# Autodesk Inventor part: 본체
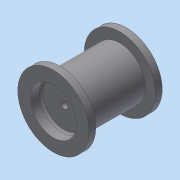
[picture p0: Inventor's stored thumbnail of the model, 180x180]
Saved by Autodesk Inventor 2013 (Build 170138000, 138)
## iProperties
Created: 2018-02
Part Number: 본체
Material: 일반
Document SubType Name: Modeling
Designer: Administrator
Density: 1 g/cm^3
Author: Administrator
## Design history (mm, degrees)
sketch "스케치3"
  geometry: L1 (0, 54)-(0, -54); L2 (0, 54)-(52.5, 54); L3 (52.5, 54)-(52.5, 44); L4 (52.5, 44)-(38, 44); L5 (38, 44)-(38, -44); L6 (38, -44)-(52.5, -44); L7 (52.5, -44)-(52.5, -54); L8 (52.5, -54)-(0, -54); L9 (37, 54)-(37, 47); L10 (37, 47)-(33, 47); L11 (33, 47)-(33, -32); L12 (33, -32)-(5, -32); L13 (5, -32)-(5, -38); L14 (5, -38)-(34, -38); L15 (34, -38)-(34, -54); 2 further points
  constraints: 30 end point, 7 perpendicular, 5 parallel, 2 equal length, 2 point on line, 1 coincident, 1 collinear, 1 horizontal, 1 midpoint, 1 vertical
  dimensions: "d0" = 108 distance of L1.start L1.end; "d2" = 10 distance of L2.end L3.end; "d3" = 76 diameter of L5 L1; "d4" = 105 diameter of L7 L1; "d5" = 68 diameter of L15 L1; "d6" = 10 diameter of L13 L1; "d7" = 16 distance between parallel lines of L8 L14; "d8" = 79 distance between parallel lines of L10 L12; "d9" = 7 distance between parallel lines of L2 L10; "d10" = 74 diameter of L9 L1; "d11" = 66 diameter of L11 L1
revolve "회전1" sketch "스케치3" stored, may be unused: angle "d12" = 90 deg
fillet "모깎기1" dims "d13" = 3
chamfer "모따기1" distance "d14" = 1; stored, may be unused: second distance "d15" = 2, angle "d16" = 45 deg
node "솔리드1"
